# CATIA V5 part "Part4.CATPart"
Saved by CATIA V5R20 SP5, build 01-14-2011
Part number: 左
Bounding box of the stored display mesh (mm): x -8.78 to 57.322, y -10 to 10, z -74.832 to -34.077
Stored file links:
  E:\180511232\很靠后、\Part4.CATPart
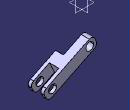
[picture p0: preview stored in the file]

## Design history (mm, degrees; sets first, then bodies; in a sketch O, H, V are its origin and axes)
Body1 (main body)
  Sketch1 on zx-plane, origin (0, 0, 0), H (-1, 0, 0), V (0, 0, 1)
    circle A1 centre (0, -42.6263) radius 5
    point P1 (0, -42.6263)
    line L1 (3.9059, -32.3796) -> (10.4771, -45.8636)
    line L2 (10.4771, -45.8636) -> (-52.4483, -76.5295)
    line L3 (-52.4483, -76.5295) -> (-59.0196, -63.0454)
    line L4 (-59.0196, -63.0454) -> (3.9059, -32.3796)
    circle A2 centre (-46.7446, -65.4066) radius 5
    point P6 (-46.7446, -65.4066)
    radius A1 = 5
    length L4 = 70
    length L3 = 15
    distance P1 L2 = 7.5
    distance P1 L1 = 8
    radius A2 = 5
    distance P6 L4 = 7.5
    distance P6 L3 = 10
    coincidence: P1 V
    parallelism: L4 L2, L1 L3
    perpendicularity: L1 L2
  Pad1: profile Sketch1, direction (0, 1, 0), length 10, mirrored extent
  Sketch2 on start face of Pad1, origin (0, -10, 0), H (1, 0, 0), V (0, 0, 1)
    line L1 (-3.9059, -32.3796) -> (-10.4771, -45.8636)
    point P1 (-3.9059, -32.3796)
    point P2 (-10.4771, -45.8636)
    line L2 (-10.4771, -45.8636) -> (16.4909, -59.0061)
    line L3 (16.4909, -59.0061) -> (23.0622, -45.5221)
    line L4 (23.0622, -45.5221) -> (-3.9059, -32.3796)
    point P3 (16.4909, -59.0061)
    reference projected point E1 (-10.4771, -45.8636) from vertex [face of Pad1 from Sketch1.L1 | start face of Pad1 | face of Pad1 from Sketch1.L2]
    reference projected line E2 (52.4483, -76.5295) -> (-10.4771, -45.8636) from edge [start face of Pad1 | face of Pad1 from Sketch1.L2]
    reference projected point E3 (-3.9059, -32.3796) from vertex [face of Pad1 from Sketch1.L1 | start face of Pad1 | face of Pad1 from Sketch1.L4]
    distance P2 E1 = 0
    distance P3 E2 = 0
    distance P1 E3 = 0
    length L4 = 30
    parallelism: L4 L2, L1 L3
  Pocket1: profile Sketch2, direction (0, 1, 0), length 10
  Sketch3 on face of Pad1 from Sketch1.L4, origin (-13.501, 0, -27.7036), H (0, 1, 0), V (-0.8989, 0, 0.4381)
    line L1 (-6, -53.62) -> (6, -53.62)
    line L2 (6, -53.62) -> (6, -93.62)
    line L3 (6, -93.62) -> (-6, -93.62)
    line L4 (-6, -93.62) -> (-6, -53.62)
    reference projected line E1 (-10, -10.6739) -> (-10, -80.6739) from edge [start face of Pad1 | face of Pad1 from Sketch1.L4]
    length L4 = 40
    length L3 = 12
    distance L4 E1 = 4
    horizontal: L1 H, L3 H
    vertical: L2 V, L4 V
  Pocket2: profile Sketch3, direction (-0.4381, 0, -0.8989), length 30
  Fillet1: radius 5, on edge [face of Pad1 from Sketch1.L4 | face of Pad1 from Sketch1.L1]
  Fillet2: radius 5, on edge [face of Pad1 from Sketch1.L1 | face of Pad1 from Sketch1.L2]
  Fillet3: radius 5, on edge [face of Pad1 from Sketch1.L3 | face of Pad1 from Sketch1.L4] (x2); edge [face of Pad1 from Sketch1.L2 | face of Pad1 from Sketch1.L3] (x2)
